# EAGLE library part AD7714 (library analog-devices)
Signal Conditioning ADC 3 V/5 V, CMOS, 500 mA Source: http://www.analog.com/UploadedFiles/Data_Sheets/39677768AD7714_c.pdf
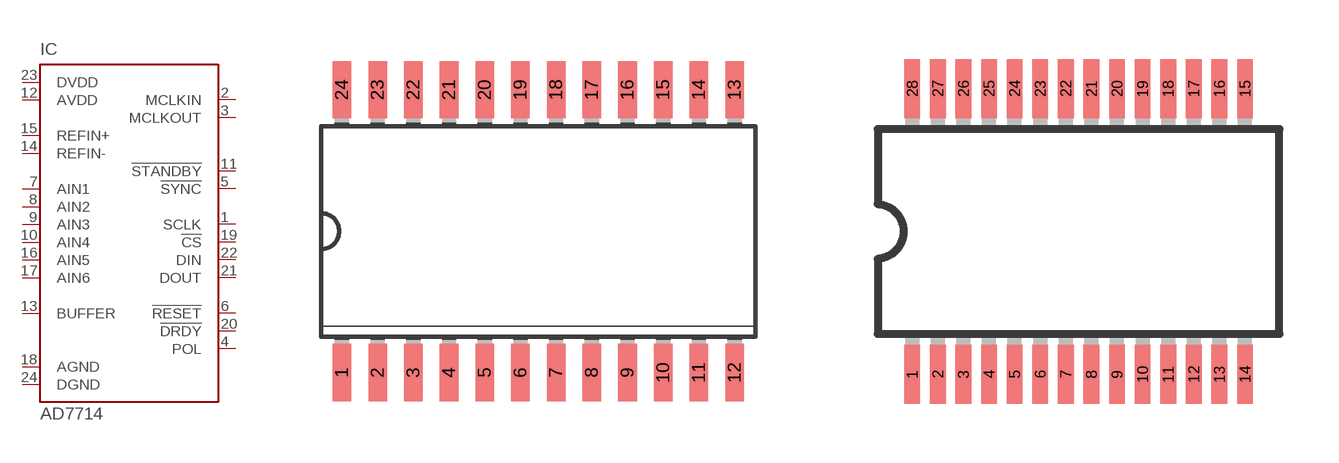
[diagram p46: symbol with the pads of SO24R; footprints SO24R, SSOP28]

Designator prefix IC

## AD7714R-24 (OC_FARNELL: unknown; OC_NEWARK: unknown)  [SO24R]
1  SCLK  in
2  MCLKIN  in
3  MCLKOUT  out
4  POL  in
5  !SYNC  in
6  !RESET  in
7  AIN1  in
8  AIN2  in
9  AIN3  in
10  AIN4  in
11  !STANDBY  in
12  AVDD  in
13  BUFFER  in
14  REFIN-  in
15  REFIN+  in
16  AIN5  in
17  AIN6  in
18  AGND  in
19  !CS  in
20  !DRDY  in
21  DOUT  out
22  DIN  in
23  DVDD  in
24  DGND  in

## AD7714RS-28 (MF: ALTERA CORPORATION; MPN: AD7714ARS-3; OC_FARNELL: 1423921; OC_NEWARK: 52F2117)  [SSOP28]
1  SCLK  in
2  MCLKIN  in
3  MCLKOUT  out
4  POL  in
5  !SYNC  in
6  !RESET  in
9  AIN1  in
10  AIN2  in
11  AIN3  in
12  AIN4  in
13  !STANDBY  in
14  AVDD  in
15  BUFFER  in
16  REFIN-  in
17  REFIN+  in
18  AIN5  in
19  AIN6  in
20  AGND  in
23  !CS  in
24  !DRDY  in
25  DOUT  out
26  DIN  in
27  DVDD  in
28  DGND  in

## AD7714RU-24 (MPN: AD7714YRUZ; OC_FARNELL: 1438857; OC_NEWARK: 19M8848)  [TSSOP24]
Pads as for SO24R

## AD7714N-24 (MF: ALTERA CORPORATION; MPN: AD7714AN-5; OC_FARNELL: unknown; OC_NEWARK: 66F5871)  [DIL24-3]
Pads as for SO24R

## Footprint SO24R (pad centres in mm)
24-Lead Wide Body SOIC (R-24) Source: http://www.analog.com/UploadedFiles/Data_Sheets/39677768AD7714_c.pdf
smd 0.66 x 2.032: 1 -6.985,-5.029; 2 -5.715,-5.029; 3 -4.445,-5.029; 4 -3.175,-5.029; 5 -1.905,-5.029; 6 -0.635,-5.029; 7 0.635,-5.029; 8 1.905,-5.029; 9 3.175,-5.029; 10 4.445,-5.029; 11 5.715,-5.029; 12 6.985,-5.029; 13 6.985,5.029; 14 5.715,5.029; 15 4.445,5.029; 16 3.175,5.029; 17 1.905,5.029; 18 0.635,5.029; 19 -0.635,5.029; 20 -1.905,5.029; 21 -3.175,5.029; 22 -4.445,5.029; 23 -5.715,5.029; 24 -6.985,5.029

## Footprint SSOP28 (pad centres in mm)
28-Lead Shrink Small Outline Package SSOP (RS-28) Source: http://www.analog.com/UploadedFiles/Data_Sheets/39677768AD7714_c.pdf
smd 0.4 x 1.5: 1 -4.225,-3.625; 2 -3.575,-3.625; 3 -2.925,-3.625; 4 -2.275,-3.625; 5 -1.625,-3.625; 6 -0.975,-3.625; 7 -0.325,-3.625; 8 0.325,-3.625; 9 0.975,-3.625; 10 1.625,-3.625; 11 2.275,-3.625; 12 2.925,-3.625; 13 3.575,-3.625; 14 4.225,-3.625; 15 4.225,3.625; 16 3.575,3.625; 17 2.925,3.625; 18 2.275,3.625; 19 1.625,3.625; 20 0.975,3.625; 21 0.325,3.625; 22 -0.325,3.625; 23 -0.975,3.625; 24 -1.625,3.625; 25 -2.275,3.625; 26 -2.925,3.625; 27 -3.575,3.625; 28 -4.225,3.625

## Footprint TSSOP24 (pad centres in mm)
24-Lead Thin Shrink Small Outline Package TSSOP (RU-24) Source: http://www.analog.com/UploadedFiles/Data_Sheets/39677768AD7714_c.pdf
smd 0.305 x 0.991: 1 -3.575,-2.918; 2 -2.925,-2.918; 3 -2.275,-2.918; 4 -1.625,-2.918; 5 -0.975,-2.918; 6 -0.325,-2.918; 7 0.325,-2.918; 8 0.975,-2.918; 9 1.625,-2.918; 10 2.275,-2.918; 11 2.925,-2.918; 12 3.575,-2.918; 13 3.575,2.918; 14 2.925,2.918; 15 2.275,2.918; 16 1.625,2.918; 17 0.975,2.918; 18 0.325,2.918; 19 -0.325,2.918; 20 -0.975,2.918; 21 -1.625,2.918; 22 -2.275,2.918; 23 -2.925,2.918; 24 -3.575,2.918

## Footprint DIL24-3 (pad centres in mm)
Dual In Line Package 0.3 inch
drill 0.813 long: 1 -13.97,-3.81; 2 -11.43,-3.81; 3 -8.89,-3.81; 4 -6.35,-3.81; 5 -3.81,-3.81; 6 -1.27,-3.81; 7 1.27,-3.81; 8 3.81,-3.81; 9 6.35,-3.81; 10 8.89,-3.81; 11 11.43,-3.81; 12 13.97,-3.81; 13 13.97,3.81; 14 11.43,3.81; 15 8.89,3.81; 16 6.35,3.81; 17 3.81,3.81; 18 1.27,3.81; 19 -1.27,3.81; 20 -3.81,3.81; 21 -6.35,3.81; 22 -8.89,3.81; 23 -11.43,3.81; 24 -13.97,3.81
